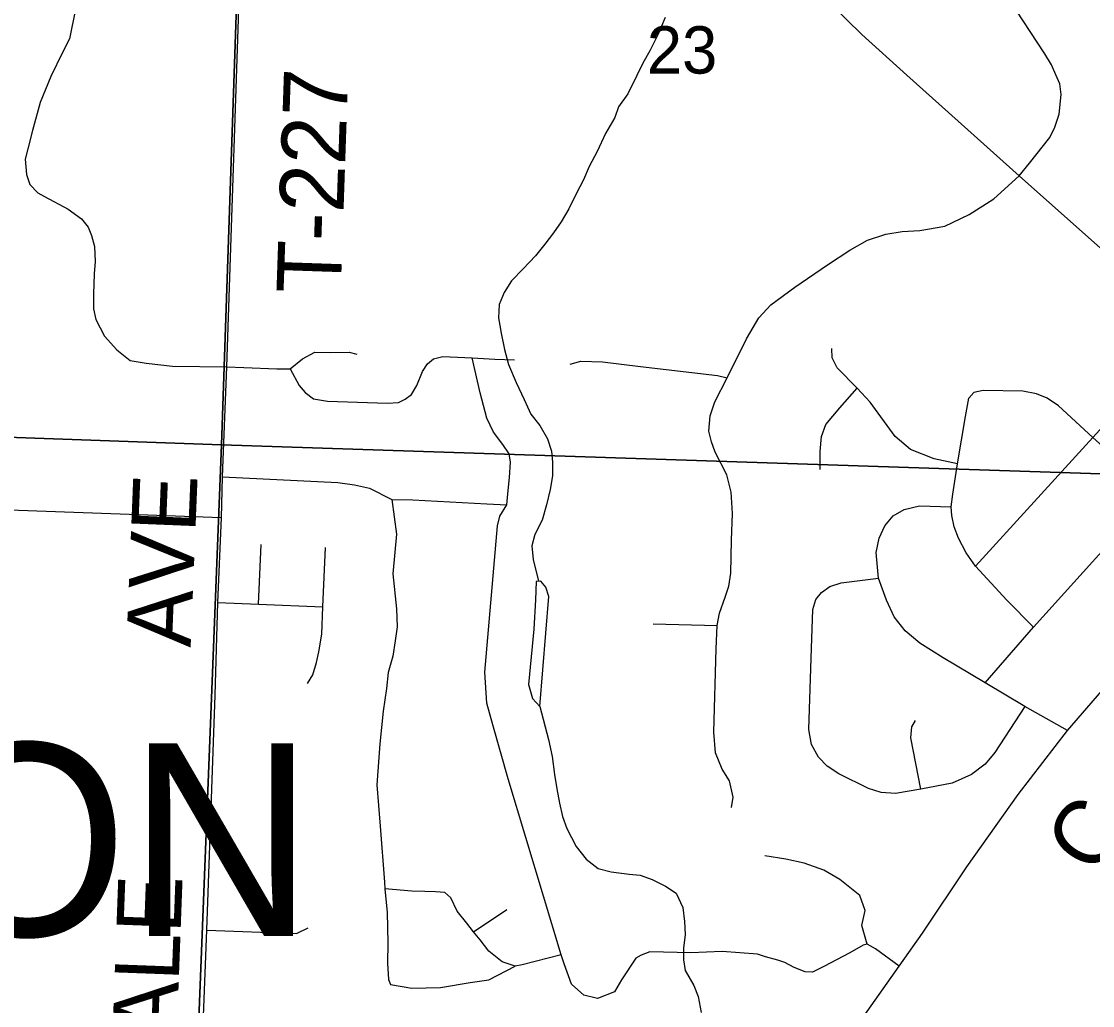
# Model space of a CAD drawing. Extents: x 0 to 34, y 0 to 22.
# Drawn here: x 7.099 to 8.046, y 16.375 to 17.244 of the extents above; entities that cross this region are included whole.
import ezdxf

# ---------------------------------------------------------------- set-up
doc = ezdxf.new("R2010")
doc.units = 0
for name, color, linetype in [('GM_X_Corporation', 7, 'Continuous'), ('GM_X_County_Road', 7, 'Continuous'), ('GM_X_County_Road_Text', 7, 'Continuous'), ('GM_X_Minor_Lake', 7, 'Continuous'), ('GM_X_Minor_River', 7, 'Continuous'), ('GM_X_Section_Text', 7, 'Continuous'), ('GM_X_State_Route', 7, 'Continuous'), ('GM_X_Township_Road', 7, 'Continuous'), ('GM_X_Township_Road_Text', 7, 'Continuous'), ('GM_X_Township_Text', 7, 'Continuous')]:
    doc.layers.add(name, color=color, linetype=linetype)

msp = doc.modelspace()

# ---------------------------------------------------------------- linework, layer by layer
at = {"layer": 'GM_X_Corporation'}
for points in [[(7.30996, 17.88061), (7.27561, 16.87038), (6.24525, 16.90712), (6.2808, 17.91168)], [(8.30127, 17.84453), (8.26687, 16.83772), (7.27561, 16.87038), (7.30996, 17.88061)], [(6.24525, 16.90712), (7.27561, 16.87038), (7.23562, 15.85593), (6.20415, 15.89115)], [(7.27561, 16.87038), (8.26687, 16.83772), (8.24089, 15.82343), (7.23562, 15.85593)]]:
    msp.add_lwpolyline(points, close=True, dxfattribs=at)
at = {"layer": 'GM_X_County_Road'}
msp.add_lwpolyline([(7.82149, 16.33451), (7.87446, 16.40953), (7.89511, 16.43878), (7.93451, 16.4973), (7.9798, 16.56129), (8.02329, 16.618), (8.0538, 16.65308), (8.08306, 16.68541), (8.14247, 16.74991), (8.16229, 16.77165), (8.2065, 16.82031), (8.25032, 16.86785)], dxfattribs=at)
at = {"layer": 'GM_X_Minor_Lake'}
for points in [[(7.5648, 16.73617), (7.56241, 16.74449), (7.55779, 16.74975), (7.55362, 16.74969), (7.55308, 16.73334), (7.55154, 16.70748), (7.54689, 16.65841), (7.55047, 16.6463), (7.55701, 16.63917)], [(7.55701, 16.63917), (7.5648, 16.73617)]]:
    msp.add_lwpolyline(points, dxfattribs=at)
at = {"layer": 'GM_X_Minor_River'}
for points in [[(7.66787, 17.24788), (7.66125, 17.23259), (7.65424, 17.21843), (7.64793, 17.20771), (7.64277, 17.19662), (7.63464, 17.18054), (7.62645, 17.16903), (7.62317, 17.15949), (7.61502, 17.14531), (7.60764, 17.12963), (7.60061, 17.11623), (7.59546, 17.10438), (7.58918, 17.09214), (7.58254, 17.07875), (7.57586, 17.06725), (7.56916, 17.05766), (7.56133, 17.04767), (7.55313, 17.0373), (7.54228, 17.02575), (7.5318, 17.01534), (7.52549, 17.005), (7.52109, 16.9943), (7.52049, 16.98251), (7.52295, 16.96887), (7.5258, 16.95447), (7.52939, 16.94122), (7.53606, 16.92536), (7.54309, 16.91026), (7.54896, 16.89742), (7.55706, 16.88728), (7.56367, 16.87559), (7.56723, 16.86462), (7.56812, 16.85514), (7.56828, 16.84298), (7.56617, 16.83079), (7.56294, 16.81745), (7.55895, 16.80371), (7.55268, 16.79109), (7.54977, 16.78117), (7.55108, 16.76903), (7.55583, 16.74972)], [(7.55701, 16.63917), (7.56462, 16.61002), (7.56786, 16.59487), (7.56997, 16.57894), (7.57204, 16.56643), (7.57449, 16.55355), (7.57692, 16.54181), (7.58086, 16.53122), (7.58904, 16.51538), (7.59792, 16.50411), (7.60865, 16.4959), (7.62007, 16.49302), (7.63604, 16.49096), (7.64553, 16.48996), (7.6562, 16.48631), (7.66804, 16.48039), (7.67761, 16.47407), (7.68347, 16.46162), (7.68478, 16.44909), (7.68532, 16.4377), (7.68396, 16.42553), (7.6841, 16.41527), (7.68537, 16.40579), (7.69314, 16.3926), (7.69706, 16.38278), (7.69953, 16.36875)]]:
    msp.add_lwpolyline(points, dxfattribs=at)
at = {"layer": 'GM_X_State_Route'}
msp.add_lwpolyline([(7.79346, 17.28064), (7.80039, 17.27344), (7.84143, 17.23298), (7.88139, 17.19708), (7.98069, 17.10817), (8.13192, 16.97351), (8.25032, 16.86785), (8.3168, 16.80825)], dxfattribs=at)
at = {"layer": 'GM_X_Township_Road'}
for p, q in [((7.30825, 16.72944), (7.31059, 16.78236)), ((7.65702, 16.71213), (7.71373, 16.71067)), ((7.49844, 16.4401), (7.52772, 16.45968))]:
    msp.add_line(p, q, dxfattribs=at)
for points in [[(7.27577, 16.80581), (7.02265, 16.81504), (7.04318, 16.85303), (7.02162, 17.21926), (7.01942, 17.23105), (7.01426, 17.23952), (7.00358, 17.2513), (7.01426, 17.26823), (7.01905, 17.28075), (7.02015, 17.29106), (7.02015, 17.2999), (7.0172, 17.308), (7.01316, 17.31978), (7.01279, 17.33083), (7.01463, 17.34335), (7.02089, 17.35623), (7.0242, 17.37022), (7.02394, 17.38398)], [(7.24673, 16.00452), (7.24847, 16.08072), (7.2561, 16.25614), (7.25863, 16.3351), (7.26276, 16.44144), (7.27018, 16.64921), (7.27252, 16.73094), (7.27577, 16.80581), (7.27645, 16.84209), (7.28028, 16.93914), (7.29305, 17.31725)], [(7.14865, 17.26529), (7.14312, 17.23804), (7.14129, 17.22921), (7.13503, 17.21705), (7.12472, 17.1957), (7.11551, 17.17287), (7.10852, 17.1482), (7.10447, 17.132), (7.10226, 17.1228), (7.10336, 17.10918), (7.10631, 17.10034), (7.1133, 17.09297), (7.1192, 17.08966), (7.14018, 17.07861), (7.15197, 17.07015), (7.15786, 17.06279), (7.1608, 17.05542), (7.16337, 17.04548), (7.16411, 17.03222), (7.16301, 17.02154), (7.16264, 17.00351), (7.16264, 16.99062), (7.16448, 16.98104), (7.17222, 16.96632), (7.18326, 16.95416), (7.19504, 16.94496), (7.20903, 16.94238), (7.23223, 16.9398), (7.28028, 16.93914), (7.2954, 16.93862)], [(7.98069, 17.10817), (7.98969, 17.11933), (8.00759, 17.14187), (8.01223, 17.15116), (8.01588, 17.16243), (8.01787, 17.18), (8.01654, 17.18928), (8.01306, 17.1974), (8.00925, 17.20619), (8.00345, 17.2158), (7.97792, 17.25443)], [(7.72651, 16.54994), (7.72773, 16.55903), (7.7245, 16.57328), (7.71818, 16.58384), (7.71227, 16.59823), (7.71067, 16.61644), (7.71276, 16.69017), (7.71373, 16.71067), (7.71575, 16.72145), (7.72082, 16.73569), (7.72402, 16.74542), (7.72582, 16.75682), (7.72638, 16.78601), (7.72735, 16.80964), (7.72596, 16.8284), (7.72221, 16.84376), (7.71199, 16.86385), (7.70859, 16.87288), (7.70623, 16.88226), (7.70755, 16.89588), (7.71172, 16.90839), (7.72249, 16.92945), (7.73972, 16.96413), (7.75063, 16.98262), (7.76127, 16.99408), (7.78236, 17.00968), (7.81117, 17.02925), (7.83097, 17.04225), (7.84661, 17.05128), (7.86273, 17.05656), (7.87733, 17.05885), (7.89276, 17.05962), (7.91499, 17.06351), (7.93654, 17.07387), (7.95823, 17.08762), (7.98069, 17.10817)], [(8.13192, 16.97351), (8.12684, 16.96637), (8.11635, 16.95402), (8.04561, 16.8769), (7.94213, 16.76304)], [(7.92598, 16.85348), (7.90547, 16.85784), (7.88447, 16.86608), (7.87091, 16.87771), (7.84894, 16.90791), (7.83731, 16.92035), (7.81987, 16.93843), (7.81535, 16.94715), (7.81503, 16.95555)], [(7.33624, 16.93744), (7.34711, 16.94643), (7.35815, 16.95232), (7.37178, 16.95196), (7.38834, 16.95232), (7.39534, 16.95048)], [(7.33624, 16.93744), (7.34416, 16.92287), (7.34969, 16.91649), (7.35704, 16.91109), (7.3692, 16.90888), (7.42221, 16.90704), (7.43215, 16.90777), (7.43805, 16.91072), (7.44357, 16.91477), (7.44836, 16.92287), (7.45314, 16.93502), (7.45756, 16.94202), (7.46309, 16.94643), (7.47118, 16.94827), (7.49732, 16.94717), (7.51721, 16.94607), (7.53451, 16.94533)], [(7.87446, 16.40953), (7.85375, 16.42497), (7.84887, 16.42767), (7.84624, 16.42921), (7.84282, 16.42811), (7.83103, 16.42139), (7.80784, 16.40948), (7.79796, 16.40427), (7.79154, 16.40471), (7.78174, 16.4086), (7.77347, 16.41286), (7.76745, 16.41481), (7.75651, 16.41796), (7.74935, 16.42031), (7.71799, 16.42252), (7.69038, 16.42128), (7.6541, 16.42239), (7.6465, 16.41943), (7.64194, 16.41682), (7.62926, 16.3976), (7.6231, 16.38703), (7.60792, 16.38111), (7.59584, 16.38389), (7.58498, 16.39386), (7.57836, 16.41176), (7.57596, 16.41971), (7.52903, 16.57504), (7.51554, 16.62299), (7.51007, 16.64202), (7.50847, 16.66936), (7.51942, 16.79879), (7.52163, 16.80726), (7.52789, 16.8172), (7.52864, 16.82701), (7.5303, 16.84142), (7.5312, 16.85512), (7.52973, 16.86249), (7.5242, 16.87059), (7.5161, 16.88163), (7.51021, 16.89378), (7.50432, 16.91624), (7.49732, 16.94717)], [(7.2954, 16.93862), (7.32465, 16.9376), (7.33624, 16.93744)], [(7.58391, 16.94147), (7.59336, 16.94439), (7.6124, 16.94356), (7.64604, 16.93967), (7.71415, 16.93174), (7.72249, 16.92945)], [(7.80469, 16.84848), (7.80485, 16.86447), (7.80593, 16.87777), (7.80986, 16.88821), (7.82208, 16.90303), (7.83731, 16.92035)], [(8.16229, 16.77165), (8.10024, 16.82764), (8.04561, 16.8769), (8.01529, 16.90476), (8.00544, 16.91154), (7.99599, 16.91526), (7.9838, 16.91784), (7.94875, 16.91833), (7.94059, 16.91671)], [(7.99332, 16.7091), (7.96966, 16.73308), (7.94213, 16.76304), (7.93365, 16.77475), (7.92695, 16.78783), (7.92315, 16.79777), (7.92113, 16.80802), (7.92057, 16.81553), (7.92186, 16.82684), (7.92598, 16.85348), (7.93316, 16.89523), (7.93615, 16.91171), (7.94059, 16.91671)], [(7.27645, 16.84209), (7.3784, 16.83708), (7.39313, 16.83487), (7.40639, 16.83193), (7.42626, 16.82199), (7.44468, 16.82162), (7.51021, 16.8183), (7.52789, 16.8172)], [(7.95061, 16.66009), (7.99332, 16.7091), (8.10024, 16.82764)], [(7.42626, 16.82199), (7.43032, 16.79143), (7.42695, 16.7563), (7.43041, 16.72553), (7.431, 16.70959), (7.42898, 16.69708), (7.42694, 16.68344), (7.42301, 16.66907), (7.42136, 16.65504), (7.4185, 16.63496), (7.41555, 16.60615), (7.4129, 16.56975), (7.41592, 16.53328), (7.41957, 16.48392), (7.42008, 16.47806), (7.42193, 16.45695), (7.42278, 16.43038), (7.42222, 16.41217), (7.4232, 16.39774), (7.42505, 16.39355), (7.44392, 16.39033), (7.46926, 16.39084), (7.49539, 16.39513), (7.51205, 16.39762), (7.53524, 16.40953)], [(8.02329, 16.618), (7.98573, 16.63917), (7.95061, 16.66009), (7.91338, 16.68221), (7.89295, 16.69521), (7.87995, 16.70603), (7.87026, 16.71839), (7.86323, 16.73308), (7.85637, 16.75263), (7.85435, 16.77516), (7.85694, 16.78775), (7.86178, 16.79874), (7.86929, 16.8077), (7.8789, 16.81327), (7.89239, 16.81634), (7.92057, 16.81553)], [(7.35171, 16.65935), (7.35642, 16.66707), (7.35967, 16.6779), (7.36165, 16.68728), (7.36418, 16.70316), (7.36526, 16.72715), (7.36742, 16.77965)], [(7.98573, 16.63917), (7.95917, 16.59831), (7.95053, 16.58814), (7.93849, 16.57909), (7.92154, 16.57134), (7.89376, 16.56593), (7.87139, 16.5623), (7.85879, 16.56319), (7.84749, 16.56674), (7.82132, 16.57974), (7.81083, 16.58652), (7.80324, 16.59427), (7.79704, 16.60539), (7.79484, 16.61866), (7.7971, 16.69077), (7.79823, 16.72477), (7.80081, 16.73373), (7.8059, 16.73987), (7.81325, 16.74512), (7.82318, 16.74835), (7.85637, 16.75263)], [(7.27252, 16.73094), (7.30825, 16.72944), (7.36526, 16.72715)], [(7.89376, 16.56593), (7.88487, 16.61154), (7.88576, 16.62108), (7.88899, 16.62674)], [(7.84624, 16.42921), (7.84149, 16.44558), (7.84466, 16.45883), (7.83988, 16.47216), (7.82226, 16.48637), (7.80798, 16.49448), (7.79065, 16.50072), (7.77443, 16.5043), (7.75593, 16.50714)], [(7.57596, 16.41971), (7.54147, 16.41078), (7.53524, 16.40953), (7.52356, 16.41345), (7.51197, 16.42288), (7.5041, 16.43299), (7.49844, 16.4401), (7.49253, 16.44752), (7.48395, 16.45824), (7.4784, 16.47005), (7.47316, 16.47466), (7.46479, 16.47544), (7.4554, 16.4756), (7.44399, 16.47601), (7.42008, 16.47806)], [(7.26276, 16.44144), (7.3418, 16.43864), (7.35227, 16.4434)]]:
    msp.add_lwpolyline(points, dxfattribs=at)

# ---------------------------------------------------------------- texts
at = {"layer": 'GM_X_County_Road_Text'}
msp.add_text('C', height=0.05682, rotation=55.32795, dxfattribs=at).set_placement((8.04738, 16.48808))
at = {"layer": 'GM_X_Section_Text'}
msp.add_text('23', height=0.041856, rotation=0.00001, dxfattribs=at).set_placement((7.65156, 17.19837))
at = {"layer": 'GM_X_Township_Road_Text'}
for s, height, rotation, p in [('T-227', 0.056818, 88.03472, (7.38095, 17.00326)), ('AVE', 0.056818, 87.65793, (7.24834, 16.69101)), ('BRUNNERDALE', 0.0568182, 87.8791, (7.22003, 15.91492))]:
    msp.add_text(s, height=height, rotation=rotation, dxfattribs=at).set_placement(p)
at = {"layer": 'GM_X_Township_Text'}
msp.add_text('JACKSON', height=0.170455, rotation=0.00001, dxfattribs=at).set_placement((6.28089, 16.43624))

doc.saveas('drawing.dxf')
